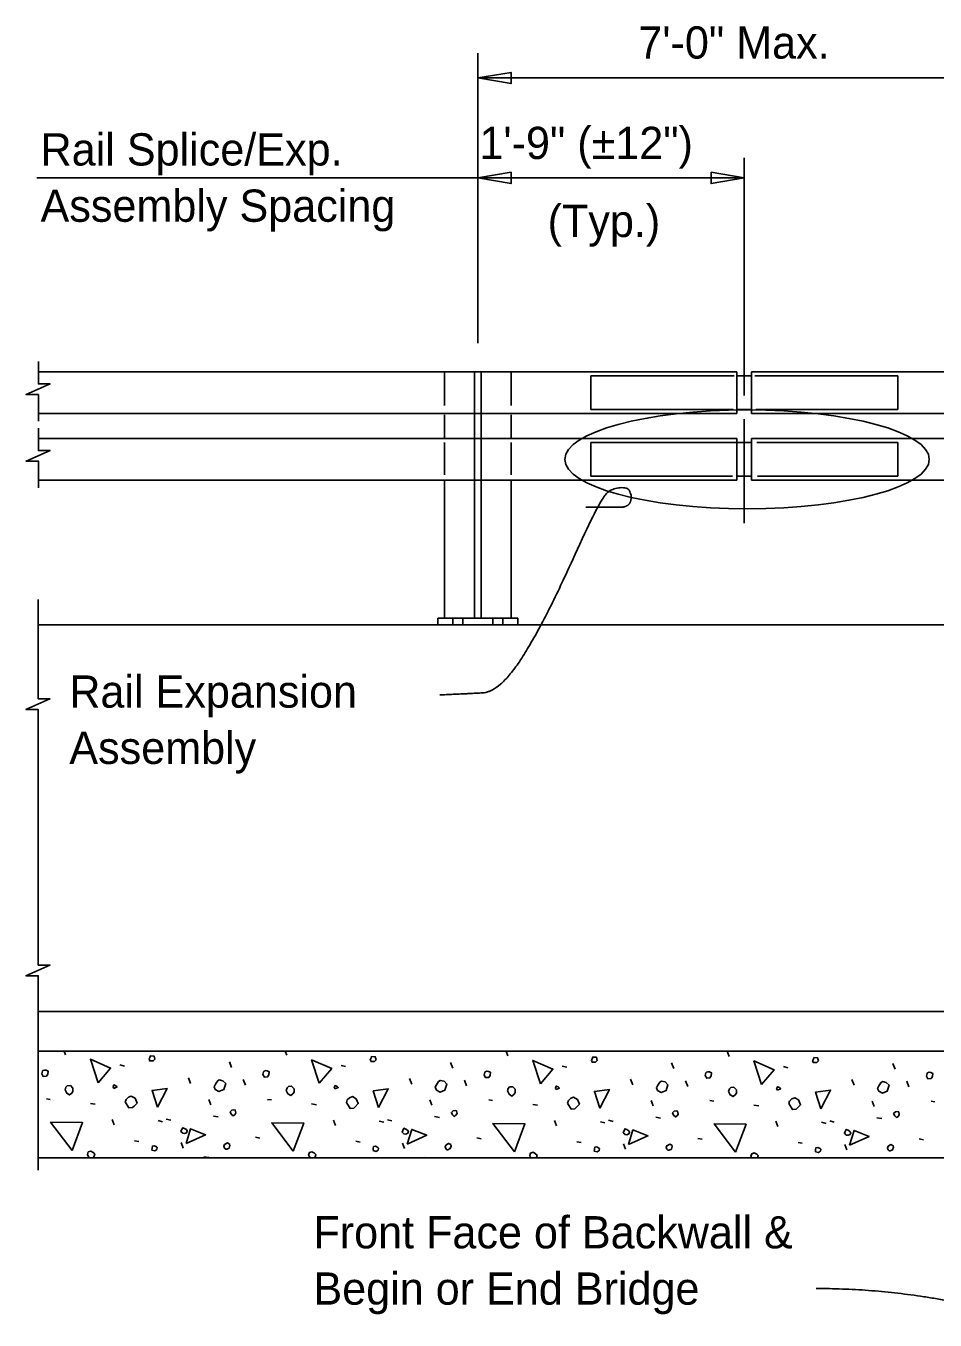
# Model space of a CAD drawing. Extents: x 120680.2 to 120752.3, y 120667.6 to 120707.3.
# Drawn here: x 120695.92 to 120701.61, y 120695.45 to 120703.54 of the extents above; entities that cross this region are included whole.
import ezdxf

# ---------------------------------------------------------------- set-up
doc = ezdxf.new("R2010")
doc.units = 0
for name, color, linetype in [('CL_Minor', 7, 'Continuous'), ('Default', 7, 'Continuous'), ('Dimension', 7, 'Continuous'), ('ParapetConc', 7, 'Continuous'), ('PedRail', 7, 'Continuous'), ('TextStructures', 7, 'Continuous')]:
    doc.layers.add(name, color=color, linetype=linetype)

msp = doc.modelspace()

# ---------------------------------------------------------------- linework, layer by layer
at = {"layer": 'CL_Minor'}
for p, q in [((120700.4127, 120702.7154), (120700.4127, 120701.2297)), ((120700.4127, 120701.0808), (120700.4127, 120700.4305))]:
    msp.add_line(p, q, dxfattribs=at)
at = {"layer": 'Default'}
msp.add_lwpolyline([(120700.2045, 120702.6252), (120700.4127, 120702.5899), (120700.2045, 120702.5546)], close=True, dxfattribs=at)
at = {"layer": 'Dimension'}
for p, q in [((120698.746, 120701.556), (120698.746, 120703.3696)), ((120698.746, 120703.2151), (120702.1898, 120703.2151))]:
    msp.add_line(p, q, dxfattribs=at)
for points in [[(120698.746, 120703.2151), (120698.9543, 120703.1798), (120698.9543, 120703.2503)], [(120698.746, 120702.5899), (120698.9543, 120702.5546), (120698.9543, 120702.6252)]]:
    msp.add_lwpolyline(points, close=True, dxfattribs=at)
for points in [[(120695.9902, 120702.5899), (120698.746, 120702.5899)], [(120698.746, 120702.5899), (120700.4127, 120702.5899)], [(120696.0007, 120701.069), (120696.0007, 120701.2356), (120695.9232, 120701.2356), (120696.0732, 120701.3018), (120696.0007, 120701.3018), (120696.0007, 120701.4427)], [(120696.0007, 120700.6523), (120696.0007, 120700.8189), (120695.9232, 120700.8189), (120696.0732, 120700.8852), (120696.0007, 120700.8852), (120696.0007, 120701.026)], [(120695.9996, 120698.3), (120695.9996, 120699.2651), (120695.9221, 120699.2651), (120696.0721, 120699.3314), (120695.9996, 120699.3314), (120695.9996, 120699.9541)], [(120695.9996, 120696.3856), (120695.9996, 120697.6005), (120695.9221, 120697.6005), (120696.0721, 120697.6668), (120695.9996, 120697.6668), (120695.9996, 120698.3)]]:
    msp.add_lwpolyline(points, dxfattribs=at)
msp.add_ellipse((120700.4302, 120700.8302), major_axis=(-1.1387, 0), ratio=0.271384, dxfattribs=at)
for points in [[(120698.509, 120699.3568), (120698.6691, 120699.3639), (120698.8854, 120699.3754), (120699.1586, 120699.8014), (120699.5112, 120700.5829), (120699.5934, 120700.6534), (120699.7051, 120700.6534), (120699.7051, 120700.5301), (120699.564, 120700.5301), (120699.423, 120700.5301)], [(120702.1768, 120695.4468), (120701.526, 120695.6444), (120700.8623, 120695.6444)]]:
    msp.add_open_spline(points, degree=2, dxfattribs=at)
at = {"layer": 'ParapetConc'}
for p, q in [((120695.9996, 120699.7946), (120702.0673, 120699.7946)), ((120695.9996, 120697.3779), (120702.0673, 120697.3779)), ((120695.9996, 120697.1279), (120702.0673, 120697.1279)), ((120695.9996, 120696.4612), (120702.0673, 120696.4612))]:
    msp.add_line(p, q, dxfattribs=at)
at = {"layer": 'PedRail'}
for p, q in [((120696.0007, 120701.3779), (120700.366, 120701.3779)), ((120698.5377, 120701.3779), (120698.5377, 120701.1671)), ((120698.7252, 120701.3779), (120698.7252, 120700.7007)), ((120698.7668, 120701.3779), (120698.7668, 120700.7007)), ((120698.9543, 120701.3779), (120698.9543, 120701.1671)), ((120699.4524, 120701.3529), (120699.4524, 120701.1424)), ((120699.4524, 120701.3529), (120700.349, 120701.3529)), ((120700.366, 120701.3779), (120700.366, 120701.1174)), ((120700.366, 120701.3529), (120700.4577, 120701.3529)), ((120700.4577, 120701.3779), (120700.4577, 120701.1174)), ((120700.4577, 120701.3779), (120705.0043, 120701.3779)), ((120700.4785, 120701.3529), (120701.373, 120701.3529)), ((120701.373, 120701.3529), (120701.373, 120701.1424)), ((120696.0007, 120701.1174), (120700.366, 120701.1174)), ((120698.5377, 120701.1084), (120698.5377, 120700.9613)), ((120698.9543, 120701.1084), (120698.9543, 120700.9613)), ((120699.4524, 120701.1424), (120700.3438, 120701.1424)), ((120700.366, 120701.1424), (120700.4577, 120701.1424)), ((120700.4577, 120701.1174), (120705.0043, 120701.1174)), ((120700.4837, 120701.1424), (120701.373, 120701.1424)), ((120696.0007, 120700.9612), (120700.366, 120700.9612)), ((120698.5377, 120700.9345), (120698.5377, 120700.7342)), ((120698.9543, 120700.9345), (120698.9543, 120700.7342)), ((120699.4524, 120700.9362), (120699.4524, 120700.7257)), ((120699.4524, 120700.9362), (120700.366, 120700.9362)), ((120700.366, 120700.9613), (120700.366, 120700.7007)), ((120700.366, 120700.9362), (120700.4577, 120700.9362)), ((120700.4577, 120700.9613), (120700.4577, 120700.7007)), ((120700.4577, 120700.9613), (120703.5869, 120700.9613)), ((120700.49, 120700.9362), (120701.373, 120700.9362)), ((120701.373, 120700.9362), (120701.373, 120700.7257)), ((120696.0007, 120700.7007), (120700.366, 120700.7007)), ((120698.5377, 120700.7007), (120698.5377, 120699.8363)), ((120698.7252, 120700.7007), (120698.7252, 120699.8363)), ((120698.7668, 120700.7007), (120698.7668, 120699.8363)), ((120698.9543, 120700.7007), (120698.9543, 120699.8363)), ((120699.4524, 120700.7257), (120700.3396, 120700.7257)), ((120700.366, 120700.7257), (120700.4577, 120700.7257)), ((120700.4577, 120700.7007), (120703.5869, 120700.7007)), ((120700.4941, 120700.7257), (120701.373, 120700.7257)), ((120698.496, 120699.7946), (120698.496, 120699.8363)), ((120698.496, 120699.8363), (120698.996, 120699.8363)), ((120698.5898, 120699.8363), (120698.5898, 120699.7946)), ((120698.6523, 120699.8363), (120698.6523, 120699.7946)), ((120698.8398, 120699.8363), (120698.8398, 120699.7946)), ((120698.9023, 120699.8363), (120698.9023, 120699.7946)), ((120698.996, 120699.7946), (120698.996, 120699.8363)), ((120696.1702, 120697.1065), (120696.1616, 120697.1279)), ((120697.5526, 120697.1029), (120697.5426, 120697.1279)), ((120698.935, 120697.0994), (120698.9235, 120697.1279)), ((120700.3174, 120697.0959), (120700.3045, 120697.1279)), ((120696.5096, 120697.0428), (120696.5379, 120697.0358)), ((120697.2079, 120697.0269), (120697.1937, 120697.0623)), ((120698.5903, 120697.0234), (120698.5761, 120697.0588)), ((120699.9726, 120697.0198), (120699.9585, 120697.0552)), ((120701.355, 120697.0163), (120701.3409, 120697.0517)), ((120696.9516, 120696.9261), (120696.9374, 120696.9615)), ((120697.892, 120697.0393), (120697.9203, 120697.0322)), ((120699.2744, 120697.0358), (120699.3027, 120697.0287)), ((120700.6568, 120697.0322), (120700.6851, 120697.0252)), ((120697.2945, 120696.9156), (120697.2804, 120696.9509)), ((120698.3339, 120696.9226), (120698.3198, 120696.958)), ((120698.6769, 120696.912), (120698.6628, 120696.9474)), ((120699.7163, 120696.9191), (120699.7022, 120696.9544)), ((120700.0593, 120696.9085), (120700.0451, 120696.9439)), ((120701.0987, 120696.9156), (120701.0846, 120696.9509)), ((120701.4417, 120696.9049), (120701.4275, 120696.9403)), ((120696.05, 120696.8307), (120696.0747, 120696.8272)), ((120696.3258, 120696.8024), (120696.3558, 120696.7971)), ((120697.0771, 120696.7936), (120697.0647, 120696.8272)), ((120697.4324, 120696.8272), (120697.4571, 120696.8236)), ((120697.7082, 120696.7989), (120697.7382, 120696.7936)), ((120698.4595, 120696.7901), (120698.4471, 120696.8236)), ((120698.8148, 120696.8236), (120698.8395, 120696.8201)), ((120699.8419, 120696.7865), (120699.8295, 120696.8201)), ((120700.1972, 120696.8201), (120700.2219, 120696.8166)), ((120701.2243, 120696.783), (120701.2119, 120696.8166)), ((120701.5796, 120696.8166), (120701.6043, 120696.813)), ((120697.0947, 120696.7229), (120697.1248, 120696.7176)), ((120698.4771, 120696.7193), (120698.5072, 120696.714)), ((120699.0906, 120696.7954), (120699.1206, 120696.7901)), ((120700.473, 120696.7918), (120700.503, 120696.7865)), ((120696.4743, 120696.6681), (120696.4619, 120696.7017)), ((120696.7483, 120696.6946), (120696.7766, 120696.6875)), ((120696.7995, 120696.7034), (120696.8278, 120696.6964)), ((120697.8567, 120696.6645), (120697.8443, 120696.6981)), ((120698.1307, 120696.691), (120698.1589, 120696.684)), ((120698.1819, 120696.6999), (120698.2102, 120696.6928)), ((120699.2391, 120696.661), (120699.2267, 120696.6946)), ((120699.5131, 120696.6875), (120699.5413, 120696.6804)), ((120699.5643, 120696.6964), (120699.5926, 120696.6893)), ((120699.8595, 120696.7158), (120699.8896, 120696.7105)), ((120700.6214, 120696.6574), (120700.6091, 120696.691)), ((120700.8955, 120696.684), (120700.9237, 120696.6769)), ((120700.9467, 120696.6928), (120700.975, 120696.6857)), ((120701.2419, 120696.7122), (120701.272, 120696.707)), ((120695.9996, 120696.5891), (120696.0023, 120696.5885)), ((120696.6016, 120696.5691), (120696.6281, 120696.5638)), ((120696.9056, 120696.5231), (120696.8932, 120696.5567)), ((120697.3581, 120696.5903), (120697.3847, 120696.585)), ((120697.9839, 120696.5655), (120698.0105, 120696.5602)), ((120698.7405, 120696.5868), (120698.7671, 120696.5815)), ((120699.3663, 120696.562), (120699.3929, 120696.5567)), ((120700.1229, 120696.5832), (120700.1494, 120696.5779)), ((120700.7487, 120696.5585), (120700.7753, 120696.5532)), ((120701.5053, 120696.5797), (120701.5318, 120696.5744)), ((120698.288, 120696.5196), (120698.2756, 120696.5532)), ((120699.6704, 120696.516), (120699.658, 120696.5496)), ((120701.0528, 120696.5125), (120701.0404, 120696.5461)), ((120697.0346, 120696.4683), (120697.0664, 120696.4648)), ((120698.417, 120696.4648), (120698.4488, 120696.4613))]:
    msp.add_line(p, q, dxfattribs=at)
for points in [[(120696.3735, 120696.9315), (120696.3258, 120697.0782), (120696.4513, 120697.0234), (120696.3735, 120696.9315)], [(120696.697, 120697.0676), (120696.7182, 120697.0676), (120696.7288, 120697.0782), (120696.7235, 120697.0977), (120696.7005, 120697.0994), (120696.697, 120697.0888), (120696.6917, 120697.0799), (120696.697, 120697.0676), (120696.6935, 120697.0711)], [(120697.7559, 120696.9279), (120697.7082, 120697.0746), (120697.8337, 120697.0198), (120697.7559, 120696.9279)], [(120698.0794, 120697.0641), (120698.1006, 120697.0641), (120698.1112, 120697.0746), (120698.1059, 120697.0941), (120698.0829, 120697.0959), (120698.0794, 120697.0853), (120698.0741, 120697.0764), (120698.0794, 120697.0641), (120698.0759, 120697.0676)], [(120699.1383, 120696.9244), (120699.0906, 120697.0711), (120699.2161, 120697.0163), (120699.1383, 120696.9244)], [(120699.4618, 120697.0605), (120699.483, 120697.0605), (120699.4936, 120697.0711), (120699.4883, 120697.0906), (120699.4653, 120697.0923), (120699.4618, 120697.0817), (120699.4565, 120697.0729), (120699.4618, 120697.0605), (120699.4583, 120697.0641)], [(120700.5207, 120696.9208), (120700.473, 120697.0676), (120700.5985, 120697.0128), (120700.5207, 120696.9208)], [(120700.8442, 120697.057), (120700.8654, 120697.057), (120700.876, 120697.0676), (120700.8707, 120697.087), (120700.8477, 120697.0888), (120700.8442, 120697.0782), (120700.8389, 120697.0693), (120700.8442, 120697.057), (120700.8406, 120697.0605)], [(120696.0217, 120696.9863), (120696.0306, 120696.9704), (120696.05, 120696.9721), (120696.0588, 120696.9845), (120696.0606, 120697.004), (120696.0482, 120697.0092), (120696.0394, 120697.011), (120696.0288, 120697.0075), (120696.0253, 120697.004), (120696.0217, 120696.9863)], [(120697.4041, 120696.9827), (120697.413, 120696.9668), (120697.4324, 120696.9686), (120697.4412, 120696.9809), (120697.443, 120697.0004), (120697.4306, 120697.0057), (120697.4218, 120697.0075), (120697.4112, 120697.004), (120697.4076, 120697.0004), (120697.4041, 120696.9827)], [(120698.7865, 120696.9792), (120698.7954, 120696.9633), (120698.8148, 120696.9651), (120698.8236, 120696.9774), (120698.8254, 120696.9969), (120698.813, 120697.0022), (120698.8042, 120697.004), (120698.7936, 120697.0004), (120698.79, 120696.9969), (120698.7865, 120696.9792)], [(120700.1689, 120696.9757), (120700.1778, 120696.9597), (120700.1972, 120696.9615), (120700.206, 120696.9739), (120700.2078, 120696.9933), (120700.1954, 120696.9986), (120700.1866, 120697.0004), (120700.176, 120696.9969), (120700.1724, 120696.9933), (120700.1689, 120696.9757)], [(120701.5513, 120696.9721), (120701.5601, 120696.9562), (120701.5796, 120696.958), (120701.5884, 120696.9704), (120701.5902, 120696.9898), (120701.5778, 120696.9951), (120701.5689, 120696.9969), (120701.5584, 120696.9933), (120701.5548, 120696.9898), (120701.5513, 120696.9721)], [(120696.1667, 120696.8873), (120696.1773, 120696.866), (120696.1949, 120696.8555), (120696.2091, 120696.866), (120696.2161, 120696.8767), (120696.2161, 120696.8979), (120696.2003, 120696.9138), (120696.1808, 120696.912), (120696.172, 120696.9032), (120696.1667, 120696.8873)], [(120696.4725, 120696.8961), (120696.4919, 120696.9049), (120696.4849, 120696.912), (120696.4725, 120696.9173), (120696.4672, 120696.9049), (120696.4725, 120696.8961)], [(120696.7447, 120696.7794), (120696.7111, 120696.8838), (120696.8048, 120696.8961), (120696.7447, 120696.7794)], [(120697.1054, 120696.8891), (120697.1283, 120696.8767), (120697.1584, 120696.8891), (120697.1708, 120696.9261), (120697.1531, 120696.9439), (120697.1301, 120696.9491), (120697.1195, 120696.9421), (120697.1071, 120696.9226), (120697.0983, 120696.9067), (120697.1054, 120696.8891)], [(120697.5491, 120696.8838), (120697.5597, 120696.8625), (120697.5773, 120696.8519), (120697.5915, 120696.8625), (120697.5985, 120696.8731), (120697.5985, 120696.8943), (120697.5826, 120696.9103), (120697.5632, 120696.9085), (120697.5544, 120696.8996), (120697.5491, 120696.8838)], [(120697.8549, 120696.8926), (120697.8743, 120696.9014), (120697.8673, 120696.9085), (120697.8549, 120696.9138), (120697.8496, 120696.9014), (120697.8549, 120696.8926)], [(120698.1271, 120696.7759), (120698.0935, 120696.8802), (120698.1872, 120696.8926), (120698.1271, 120696.7759)], [(120698.4878, 120696.8855), (120698.5107, 120696.8731), (120698.5408, 120696.8855), (120698.5532, 120696.9226), (120698.5355, 120696.9403), (120698.5125, 120696.9456), (120698.5019, 120696.9385), (120698.4895, 120696.9191), (120698.4807, 120696.9032), (120698.4878, 120696.8855)], [(120698.9314, 120696.8802), (120698.9421, 120696.859), (120698.9597, 120696.8484), (120698.9739, 120696.859), (120698.9809, 120696.8696), (120698.9809, 120696.8908), (120698.965, 120696.9067), (120698.9456, 120696.9049), (120698.9368, 120696.8961), (120698.9314, 120696.8802)], [(120699.2373, 120696.8891), (120699.2567, 120696.8979), (120699.2496, 120696.9049), (120699.2373, 120696.9103), (120699.232, 120696.8979), (120699.2373, 120696.8891)], [(120699.5095, 120696.7723), (120699.4759, 120696.8767), (120699.5696, 120696.8891), (120699.5095, 120696.7723)], [(120699.8701, 120696.882), (120699.8931, 120696.8696), (120699.9232, 120696.882), (120699.9356, 120696.9191), (120699.9179, 120696.9368), (120699.8949, 120696.9421), (120699.8843, 120696.935), (120699.8719, 120696.9156), (120699.8631, 120696.8996), (120699.8701, 120696.882)], [(120700.3138, 120696.8767), (120700.3245, 120696.8555), (120700.3421, 120696.8448), (120700.3563, 120696.8555), (120700.3633, 120696.866), (120700.3633, 120696.8873), (120700.3474, 120696.9032), (120700.328, 120696.9014), (120700.3192, 120696.8926), (120700.3138, 120696.8767)], [(120700.6197, 120696.8855), (120700.6391, 120696.8943), (120700.632, 120696.9014), (120700.6197, 120696.9067), (120700.6144, 120696.8943), (120700.6197, 120696.8855)], [(120700.8919, 120696.7689), (120700.8583, 120696.8731), (120700.952, 120696.8855), (120700.8919, 120696.7689)], [(120701.2525, 120696.8784), (120701.2755, 120696.866), (120701.3056, 120696.8784), (120701.318, 120696.9156), (120701.3003, 120696.9332), (120701.2773, 120696.9385), (120701.2667, 120696.9315), (120701.2543, 120696.912), (120701.2455, 120696.8961), (120701.2525, 120696.8784)], [(120696.5432, 120696.8112), (120696.5662, 120696.7741), (120696.5892, 120696.7759), (120696.598, 120696.7847), (120696.6174, 120696.8042), (120696.6051, 120696.8342), (120696.5803, 120696.8484), (120696.5626, 120696.8413), (120696.5485, 120696.8272), (120696.5432, 120696.8112)], [(120697.9256, 120696.8077), (120697.9486, 120696.7706), (120697.9716, 120696.7723), (120697.9804, 120696.7812), (120697.9998, 120696.8006), (120697.9874, 120696.8307), (120697.9627, 120696.8448), (120697.945, 120696.8378), (120697.9309, 120696.8236), (120697.9256, 120696.8077)], [(120699.308, 120696.8042), (120699.331, 120696.7671), (120699.3539, 120696.7689), (120699.3628, 120696.7777), (120699.3822, 120696.7971), (120699.3698, 120696.8272), (120699.3451, 120696.8413), (120699.3274, 120696.8342), (120699.3133, 120696.8201), (120699.308, 120696.8042)], [(120700.6904, 120696.8006), (120700.7134, 120696.7635), (120700.7363, 120696.7653), (120700.7452, 120696.7741), (120700.7646, 120696.7936), (120700.7522, 120696.8236), (120700.7275, 120696.8378), (120700.7098, 120696.8307), (120700.6957, 120696.8166), (120700.6904, 120696.8006)], [(120697.2061, 120696.7353), (120697.2167, 120696.7246), (120697.2273, 120696.7317), (120697.2344, 120696.7423), (120697.2309, 120696.76), (120697.222, 120696.7618), (120697.2096, 120696.76), (120697.1991, 120696.7494), (120697.2061, 120696.7353)], [(120698.5885, 120696.7317), (120698.5991, 120696.7211), (120698.6097, 120696.7282), (120698.6168, 120696.7388), (120698.6133, 120696.7565), (120698.6044, 120696.7582), (120698.592, 120696.7565), (120698.5814, 120696.7458), (120698.5885, 120696.7317)], [(120699.9709, 120696.7282), (120699.9815, 120696.7176), (120699.9921, 120696.7246), (120699.9992, 120696.7353), (120699.9957, 120696.7529), (120699.9868, 120696.7547), (120699.9744, 120696.7529), (120699.9638, 120696.7423), (120699.9709, 120696.7282)], [(120701.3533, 120696.7246), (120701.3639, 120696.714), (120701.3745, 120696.7211), (120701.3816, 120696.7317), (120701.3781, 120696.7494), (120701.3692, 120696.7511), (120701.3568, 120696.7494), (120701.3462, 120696.7388), (120701.3533, 120696.7246)], [(120696.2109, 120696.5072), (120696.0765, 120696.684), (120696.2762, 120696.6822), (120696.2109, 120696.5072)], [(120696.9021, 120696.6151), (120696.9144, 120696.6133), (120696.9268, 120696.6186), (120696.9304, 120696.6292), (120696.925, 120696.638), (120696.9144, 120696.6451), (120696.9021, 120696.6504), (120696.895, 120696.6363), (120696.8914, 120696.6256), (120696.9021, 120696.6151)], [(120696.9233, 120696.5514), (120696.9516, 120696.6433), (120697.0453, 120696.6062), (120696.9233, 120696.5514)], [(120697.5933, 120696.5036), (120697.4589, 120696.6804), (120697.6586, 120696.6787), (120697.5933, 120696.5036)], [(120698.2845, 120696.6115), (120698.2968, 120696.6097), (120698.3092, 120696.6151), (120698.3128, 120696.6256), (120698.3074, 120696.6345), (120698.2968, 120696.6416), (120698.2845, 120696.6469), (120698.2774, 120696.6327), (120698.2738, 120696.6221), (120698.2845, 120696.6115)], [(120698.3057, 120696.5479), (120698.3339, 120696.6398), (120698.4276, 120696.6027), (120698.3057, 120696.5479)], [(120698.9757, 120696.5001), (120698.8413, 120696.6769), (120699.041, 120696.6752), (120698.9757, 120696.5001)], [(120699.6669, 120696.608), (120699.6792, 120696.6062), (120699.6916, 120696.6115), (120699.6951, 120696.6221), (120699.6898, 120696.6309), (120699.6792, 120696.638), (120699.6669, 120696.6433), (120699.6598, 120696.6292), (120699.6562, 120696.6186), (120699.6669, 120696.608)], [(120700.3581, 120696.4966), (120700.2237, 120696.6734), (120700.4234, 120696.6716), (120700.3581, 120696.4966)], [(120701.0493, 120696.6044), (120701.0616, 120696.6027), (120701.074, 120696.608), (120701.0775, 120696.6186), (120701.0722, 120696.6274), (120701.0616, 120696.6345), (120701.0493, 120696.6398), (120701.0422, 120696.6256), (120701.0386, 120696.6151), (120701.0493, 120696.6044)], [(120699.6881, 120696.5443), (120699.7163, 120696.6363), (120699.81, 120696.5991), (120699.6881, 120696.5443)], [(120701.0705, 120696.5408), (120701.0987, 120696.6327), (120701.1924, 120696.5956), (120701.0705, 120696.5408)], [(120696.3429, 120696.4613), (120696.3487, 120696.4718), (120696.3523, 120696.486), (120696.3434, 120696.4948), (120696.3275, 120696.5036), (120696.3116, 120696.4984), (120696.3063, 120696.4824), (120696.3098, 120696.4754)], [(120696.3098, 120696.4754), (120696.3177, 120696.4613)], [(120696.7094, 120696.5107), (120696.7288, 120696.5054), (120696.7412, 120696.5143), (120696.743, 120696.5267), (120696.7394, 120696.5302), (120696.7253, 120696.5372), (120696.7129, 120696.5355), (120696.7111, 120696.5231), (120696.7094, 120696.5107)], [(120697.1708, 120696.516), (120697.1778, 120696.516), (120697.192, 120696.5231), (120697.1973, 120696.539), (120697.1955, 120696.5479), (120697.1813, 120696.5549), (120697.1637, 120696.5443), (120697.1601, 120696.5337), (120697.1637, 120696.5231), (120697.1708, 120696.516)], [(120697.7272, 120696.4613), (120697.7311, 120696.4683), (120697.7347, 120696.4824), (120697.7258, 120696.4913), (120697.7099, 120696.5001), (120697.694, 120696.4948), (120697.6887, 120696.4789), (120697.6922, 120696.4718)], [(120698.0918, 120696.5072), (120698.1112, 120696.5019), (120698.1236, 120696.5107), (120698.1254, 120696.5231), (120698.1218, 120696.5267), (120698.1076, 120696.5337), (120698.0953, 120696.5319), (120698.0935, 120696.5196), (120698.0918, 120696.5072)], [(120698.5532, 120696.5125), (120698.5602, 120696.5125), (120698.5744, 120696.5196), (120698.5797, 120696.5355), (120698.5779, 120696.5443), (120698.5637, 120696.5514), (120698.5461, 120696.5408), (120698.5425, 120696.5302), (120698.5461, 120696.5196), (120698.5532, 120696.5125)], [(120699.1116, 120696.4613), (120699.1135, 120696.4648), (120699.1171, 120696.4789), (120699.1082, 120696.4878), (120699.0923, 120696.4966), (120699.0764, 120696.4913), (120699.0711, 120696.4754), (120699.0746, 120696.4683)], [(120699.4742, 120696.5036), (120699.4936, 120696.4984), (120699.506, 120696.5072), (120699.5078, 120696.5196), (120699.5042, 120696.5231), (120699.49, 120696.5302), (120699.4777, 120696.5284), (120699.4759, 120696.516), (120699.4742, 120696.5036)], [(120699.9356, 120696.509), (120699.9426, 120696.509), (120699.9568, 120696.516), (120699.9621, 120696.5319), (120699.9603, 120696.5408), (120699.9461, 120696.5479), (120699.9285, 120696.5372), (120699.9249, 120696.5267), (120699.9285, 120696.516), (120699.9356, 120696.509)], [(120700.4959, 120696.4613), (120700.4995, 120696.4754), (120700.4906, 120696.4842), (120700.4747, 120696.4931), (120700.4588, 120696.4878), (120700.4535, 120696.4718), (120700.457, 120696.4648)], [(120700.8566, 120696.5001), (120700.876, 120696.4948), (120700.8884, 120696.5036), (120700.8901, 120696.516), (120700.8866, 120696.5196), (120700.8724, 120696.5267), (120700.8601, 120696.5249), (120700.8583, 120696.5125), (120700.8566, 120696.5001)], [(120701.318, 120696.5054), (120701.325, 120696.5054), (120701.3392, 120696.5125), (120701.3445, 120696.5284), (120701.3427, 120696.5372), (120701.3285, 120696.5443), (120701.3109, 120696.5337), (120701.3073, 120696.5231), (120701.3109, 120696.5125), (120701.318, 120696.5054)], [(120697.6922, 120696.4718), (120697.6981, 120696.4613)], [(120699.0746, 120696.4683), (120699.0786, 120696.4613)], [(120700.457, 120696.4648), (120700.459, 120696.4613)]]:
    msp.add_lwpolyline(points, dxfattribs=at)

# ---------------------------------------------------------------- texts
at = {"layer": 'Dimension'}
for s, p in [('Front Face of Backwall &', (120697.7193, 120695.8955)), ('Begin or End Bridge', (120697.7193, 120695.5435))]:
    msp.add_text(s, height=0.2016, dxfattribs=at).set_placement(p)
at = {"layer": 'TextStructures'}
for s, p in [('7\'-0" Max.', (120699.7501, 120703.3364)), ('Rail Splice/Exp.', (120696.0136, 120702.6678)), ('1\'-9" (±12")', (120698.7567, 120702.7083)), ('Assembly Spacing', (120696.0136, 120702.3158)), ('(Typ.)', (120699.1832, 120702.2206)), ('Rail Expansion ', (120696.1934, 120699.2773)), ('Assembly', (120696.1934, 120698.9253))]:
    msp.add_text(s, height=0.2016, dxfattribs=at).set_placement(p)

doc.saveas('drawing.dxf')
